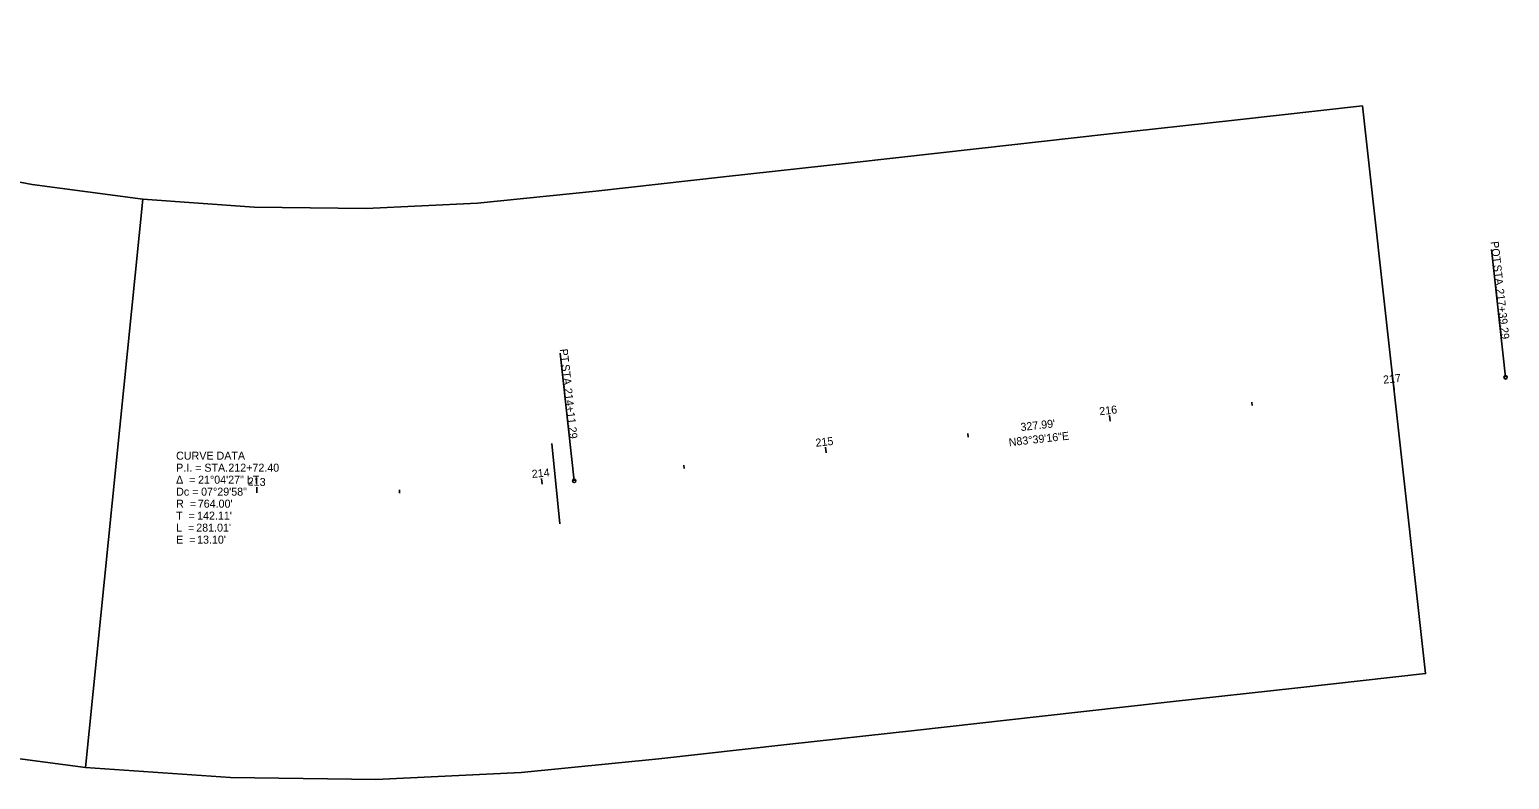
# Model space of a CAD drawing. Extents: x 1600023 to 1602105, y 286460 to 286887.
# Drawn here: x 1601587 to 1602105, y 286624 to 286887 of the extents above; entities that cross this region are included whole.
import ezdxf

# ---------------------------------------------------------------- set-up
doc = ezdxf.new("R2010")
doc.units = 0
for name, color, linetype in [('DT_X_Contour_Minor', 7, 'Continuous'), ('DT_X_Island', 7, 'Continuous'), ('DT_X_Terrain_Boundary', 7, 'Continuous'), ('DT_X_Void', 7, 'Continuous'), ('GE_P_Alignment_100_Stations', 7, 'Continuous'), ('SC_Scratch3', 7, 'Continuous'), ('UT_X_Overhead_Electric', 7, 'Continuous')]:
    doc.layers.add(name, color=color, linetype=linetype)

msp = doc.modelspace()

# ---------------------------------------------------------------- linework, layer by layer
at = {"layer": 'DT_X_Island'}
for p, q in [((1602103.63, 286765.08), (1602098.66, 286809.8)), ((1601777.65, 286728.82), (1601772.68, 286773.55))]:
    msp.add_line(p, q, dxfattribs=at)
for centre in [(1602103.63, 286765.08), (1601777.65, 286728.82)]:
    msp.add_circle(centre, 0.6, dxfattribs=at)
at = {"layer": 'GE_P_Alignment_100_Stations'}
msp.add_line((1601769.77, 286741.91), (1601772.66, 286713.8), dxfattribs=at)
at = {"layer": 'SC_Scratch3'}
for p, q in [((1602064.59, 286760.73), (1602064.37, 286762.72)), ((1602014.89, 286755.21), (1602014.76, 286756.4)), ((1601965.2, 286749.68), (1601964.98, 286751.67)), ((1601915.51, 286744.16), (1601915.37, 286745.35)), ((1601865.81, 286738.63), (1601865.59, 286740.62)), ((1601816.12, 286733.1), (1601815.99, 286734.3)), ((1601616.66, 286727.99), (1601616.78, 286729.18)), ((1601766.42, 286727.66), (1601766.22, 286729.65)), ((1601666.53, 286724.61), (1601666.6, 286726.61)), ((1601716.53, 286724.5), (1601716.49, 286725.7))]:
    msp.add_line(p, q, dxfattribs=at)
at = {"layer": 'UT_X_Overhead_Electric'}
for points in [[(1601137.18, 286850.71), (1601216.59, 286667.15), (1601246.49, 286677.8), (1601277.54, 286684.41), (1601309.18, 286686.86), (1601340.88, 286685.12), (1601372.06, 286679.21), (1601415.24, 286667.86), (1601458.76, 286656.42), (1601506.2, 286644.63), (1601556.18, 286635.08), (1601606.63, 286628.49), (1601626.67, 286827.49), (1601587.9, 286832.55), (1601549.49, 286839.88), (1601509.61, 286849.85), (1601466.08, 286861.29), (1601422.21, 286872.82), (1601365.04, 286883.66), (1601306.93, 286886.85), (1601248.92, 286882.35), (1601192, 286870.23)], [(1601626.67, 286827.49), (1601606.63, 286628.49), (1601657.39, 286624.89), (1601708.26, 286624.28), (1601759.09, 286626.66), (1601807.29, 286631.5), (1601852.01, 286636.48), (1601896.74, 286641.45), (1601941.46, 286646.42), (1601986.19, 286651.4), (1602030.91, 286656.37), (1602075.63, 286661.35), (1602053.53, 286860.12), (1602008.8, 286855.15), (1601964.08, 286850.17), (1601919.36, 286845.2), (1601874.63, 286840.23), (1601829.91, 286835.25), (1601785.18, 286830.28), (1601743.84, 286826.08), (1601704.78, 286824.24), (1601665.68, 286824.72)]]:
    msp.add_lwpolyline(points, close=True, dxfattribs=at)

# ---------------------------------------------------------------- texts
at = {"layer": 'DT_X_Contour_Minor'}
msp.add_text("327.99'", height=2.8, rotation=6.3456, dxfattribs=at).set_placement((1601934, 286746.25))
at = {"layer": 'DT_X_Island'}
for s, p in [('POT', (1602098.4, 286812.56)), (' STA. ', (1602099.19, 286805.4)), ('217+39.29', (1602100.24, 286796.01)), ('PT', (1601772.57, 286774.92)), (' STA. ', (1601773.05, 286770.54)), ('214+11.29', (1601774.1, 286761.14))]:
    msp.add_text(s, height=2.8, rotation=276.3456, dxfattribs=at).set_placement(p)
at = {"layer": 'DT_X_Terrain_Boundary'}
for s, p in [('CURVE DATA', (1601638.31, 286736.24)), ('P.I. = STA. ', (1601638.31, 286732.04)), ('212+72.40', (1601656.58, 286732.04)), ('Δ  = ', (1601638.31, 286727.84)), ('21°04\'27" LT', (1601645.99, 286727.84)), ('Dc = ', (1601638.31, 286723.64)), ('07°29\'58"', (1601647.05, 286723.64)), ('T  = ', (1601638.31, 286715.24)), ('R  = ', (1601638.31, 286719.44)), ("142.11'", (1601645.65, 286715.24)), ("764.00'", (1601645.89, 286719.44)), ('L  = ', (1601638.31, 286711.04)), ("281.01'", (1601645.35, 286711.04)), ('E  = ', (1601638.31, 286706.84)), ("13.10'", (1601645.65, 286706.84))]:
    msp.add_text(s, height=2.8, dxfattribs=at).set_placement(p)
at = {"layer": 'DT_X_Void'}
msp.add_text('N83°39\'16"E', height=2.8, rotation=6.3456, dxfattribs=at).set_placement((1601929.88, 286740.92))
at = {"layer": 'SC_Scratch3'}
for s, rotation, p in [('217', 6.3456, (1602060.92, 286762.84)), ('216', 6.3456, (1601961.59, 286751.79)), ('215', 6.3456, (1601862.25, 286740.75)), ('214', 5.4985, (1601762.92, 286729.83)), ('213', 357.9991, (1601663.35, 286727.22))]:
    msp.add_text(s, height=2.8, rotation=rotation, dxfattribs=at).set_placement(p)

doc.saveas('drawing.dxf')
